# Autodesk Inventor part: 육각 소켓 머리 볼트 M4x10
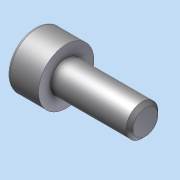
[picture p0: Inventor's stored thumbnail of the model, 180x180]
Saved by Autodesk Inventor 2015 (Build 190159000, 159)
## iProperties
Created: 2024-06
Part Number: 육각 소켓 머리 볼트 M4x10
Material: 일반
Document SubType Name: Modeling
Designer: Administrator
Density: 1 g/cm^3
Appearance: 기본값
Author: Administrator
Author: jhkim
Description: 6각머리 태핑 나사
Creation Date: 2024-05-30
Sending System: Autodesk Inventor 2025
Preprocessor: ST-DEVELOPER v20
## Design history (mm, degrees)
node "육각 소켓 머리 볼트 M4x101"
body "Solid1"
node "기준1"
